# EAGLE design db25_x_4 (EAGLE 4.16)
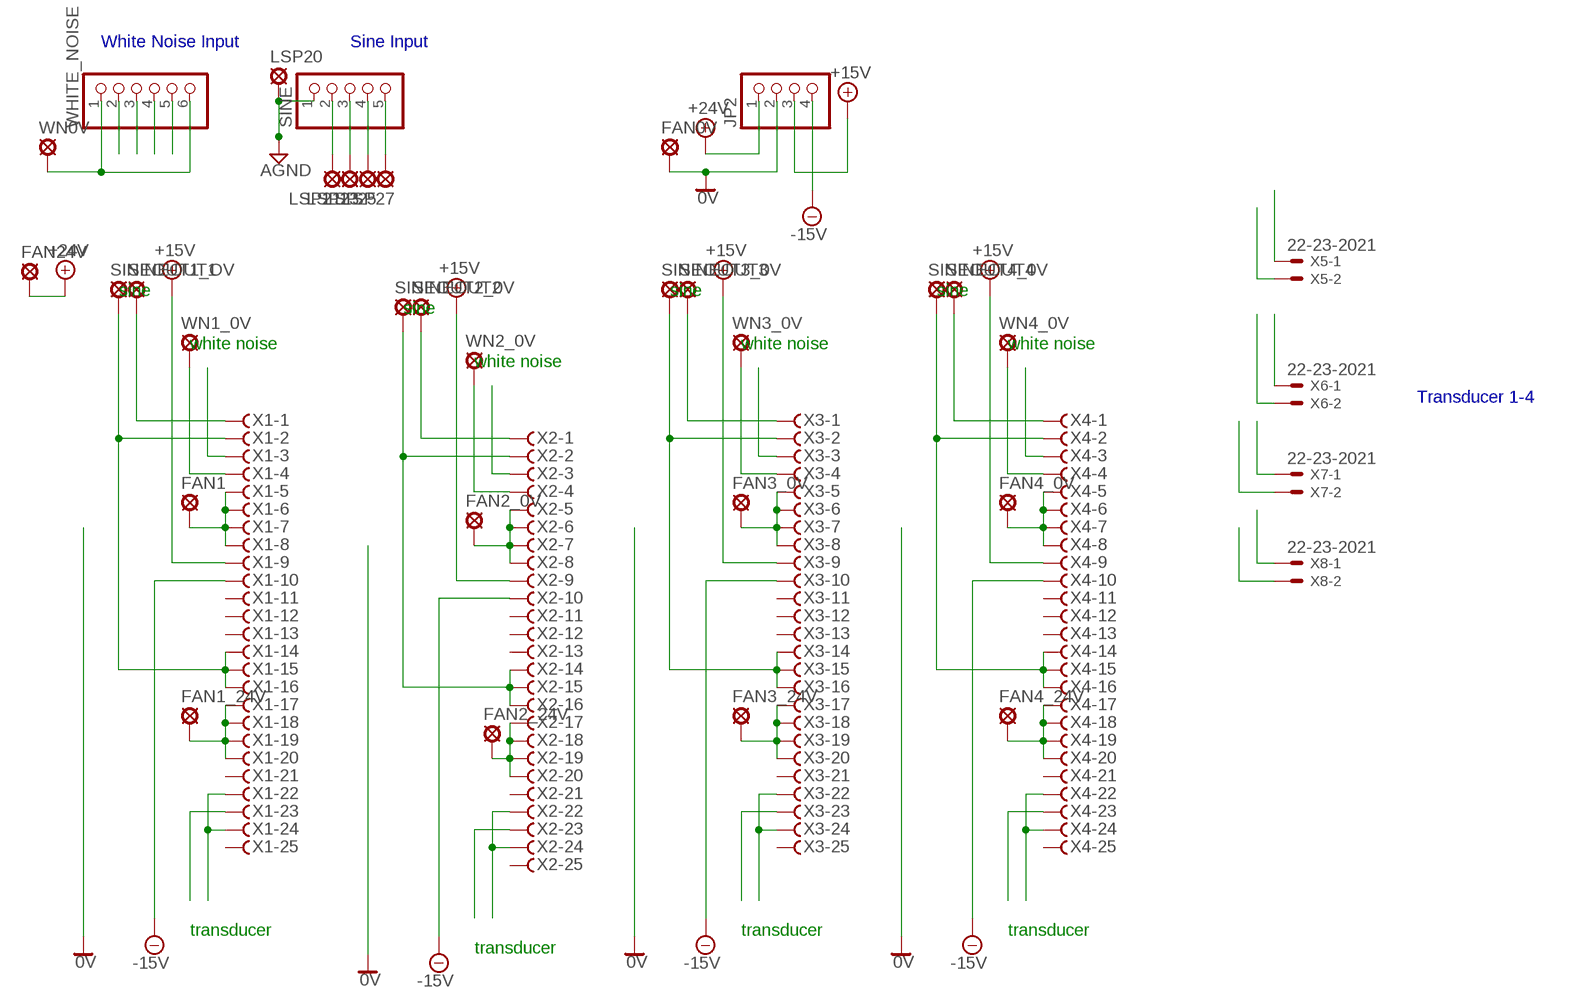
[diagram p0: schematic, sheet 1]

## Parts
FAN0V  SE14  [SE14]
FAN1  SE14  [SE14]
FAN1_24V  SE14  [SE14]
FAN2_0V  SE14  [SE14]
FAN2_24V  SE14  [SE14]
FAN3_0V  SE14  [SE14]
FAN3_24V  SE14  [SE14]
FAN4_0V  SE14  [SE14]
FAN4_24V  SE14  [SE14]
FAN24V  SE14  [SE14]
JP2  PINHD-1X4  [1X04]
LSP20  SE14  [SE14]
LSP21  SE14  [SE14]
LSP23  SE14  [SE14]
LSP25  SE14  [SE14]
LSP27  SE14  [SE14]
SINE  PINHD-1X5  [1X05]
SINEOUT1  SE14  [SE14]
SINEOUT1_OV  SE14  [SE14]
SINEOUT2  SE14  [SE14]
SINEOUT2_0V  SE14  [SE14]
SINEOUT3  SE14  [SE14]
SINEOUT3_0V  SE14  [SE14]
SINEOUT4  SE14  [SE14]
SINEOUT4_0V  SE14  [SE14]
WHITE_NOISE  PINHD-1X6  [1X06]
WN0V  SE14  [SE14]
WN1_0V  SE14  [SE14]
WN2_0V  SE14  [SE14]
WN3_0V  SE14  [SE14]
WN4_0V  SE14  [SE14]
X1  F25VS  [F25V]
X2  F25VS  [F25V]
X3  F25VS  [F25V]
X4  F25VS  [F25V]
X5  22-23-2021  [22-23-2021]
X6  22-23-2021  [22-23-2021]
X7  22-23-2021  [22-23-2021]
X8  22-23-2021  [22-23-2021]

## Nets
0V [power]: FAN0V.MP JP2.2
+15V [power]: JP2.3 X1.9 X2.9 X3.9 X4.9
+24V [power]: FAN24V.MP JP2.1
-15V [power]: JP2.4 X1.10 X2.10 X3.10 X4.10
AGND [power]: LSP20.MP SINE.1
N$1 [power]: FAN1_24V.MP X1.17 X1.18 X1.19 X1.20
N$2 [power]: FAN2_24V.MP X2.17 X2.18 X2.19 X2.20
N$3 [power]: FAN3_24V.MP X3.17 X3.18 X3.19 X3.20
N$4 [power]: FAN4_24V.MP X4.17 X4.18 X4.19 X4.20
N$5 [power]: FAN1.MP X1.5 X1.6 X1.7 X1.8
N$6 [power]: FAN2_0V.MP X2.5 X2.6 X2.7 X2.8
N$7 [power]: FAN3_0V.MP X3.5 X3.6 X3.7 X3.8
N$8 [power]: FAN4_0V.MP X4.5 X4.6 X4.7 X4.8
N$9 [power]: SINEOUT1_OV.MP X1.2 X1.14 X1.15 X1.16
N$10 [power]: SINEOUT2_0V.MP X2.2 X2.14 X2.15 X2.16
N$11 [power]: SINEOUT3_0V.MP X3.2 X3.14 X3.15 X3.16
N$12 [power]: SINEOUT4_0V.MP X4.2 X4.14 X4.15 X4.16
S1 [AF_OUT]: LSP21.MP SINE.2
S1_A [AF_OUT]: SINEOUT1.MP X1.1
S2 [AF_OUT]: LSP23.MP SINE.3
S2_A [AF_OUT]: SINEOUT2.MP X2.1
S3 [AF_OUT]: LSP25.MP SINE.4
S3_A [AF_OUT]: SINEOUT3.MP X3.1
S4 [AF_OUT]: LSP27.MP SINE.5
S4_A [AF_OUT]: SINEOUT4.MP X4.1
T1: X1.23 X5.1
T1_GND: X1.22 X1.24 X5.2
T2: X2.23 X6.1
T2_GND: X2.22 X2.24 X6.2
T3: X3.23 X7.1
T3_GND: X3.22 X3.24 X7.2
T4: X4.23 X8.1
T4_GND: X4.22 X4.24 X8.2
WN1 [AF_OUT]: WHITE_NOISE.2 X1.3
WN2 [AF_OUT]: WHITE_NOISE.3 X2.3
WN3 [AF_OUT]: WHITE_NOISE.4 X3.3
WN4 [AF_OUT]: WHITE_NOISE.5 X4.3
WN_GND [power]: WHITE_NOISE.1 WHITE_NOISE.6 WN0V.MP
WN_GND_1 [power]: WN1_0V.MP X1.4
WN_GND_2 [power]: WN2_0V.MP X2.4
WN_GND_3 [power]: WN3_0V.MP X3.4
WN_GND_4 [power]: WN4_0V.MP X4.4
Unconnected: X1.11 X1.12 X1.13 X1.21 X1.25 X2.11 X2.12 X2.13 X2.21 X2.25 X3.11 X3.12 X3.13 X3.21 X3.25 X4.11 X4.12 X4.13 X4.21 X4.25

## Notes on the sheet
- White Noise Input | Sine Input
- sine | sine | sine
- sine
- white noise | white noise | white noise
- white noise
- Transducer 1-4
- transducer | transducer | transducer
- transducer

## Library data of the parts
FAN0V FAN1 FAN1_24V FAN2_0V FAN2_24V FAN3_0V FAN3_24V FAN4_0V FAN4_24V FAN24V LSP20 LSP21 LSP23 LSP25 LSP27 SINEOUT1 SINEOUT1_OV SINEOUT2 SINEOUT2_0V SINEOUT3 SINEOUT3_0V SINEOUT4 SINEOUT4_0V WN0V WN1_0V WN2_0V WN3_0V WN4_0V = solpad:SE14: SOLDER PAD
JP2 = pinhead:PINHD-1X4: PIN HEADER
SINE = pinhead:PINHD-1X5: PIN HEADER
WHITE_NOISE = pinhead:PINHD-1X6: PIN HEADER
X1-X4 = con-subd:F25?S: SUB-D
X5-X8 = con-molex:22-23-2021: .100" (2.54mm) Center Header - 2 Pin

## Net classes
0 default: width 0.61 mm, drill 0.254 mm, clearance 0.711 mm
1 power: width 1.016 mm, drill 0.305 mm, clearance 0.813 mm
2 AF_OUT: width 1.016 mm, drill 0.305 mm, clearance 0.813 mm

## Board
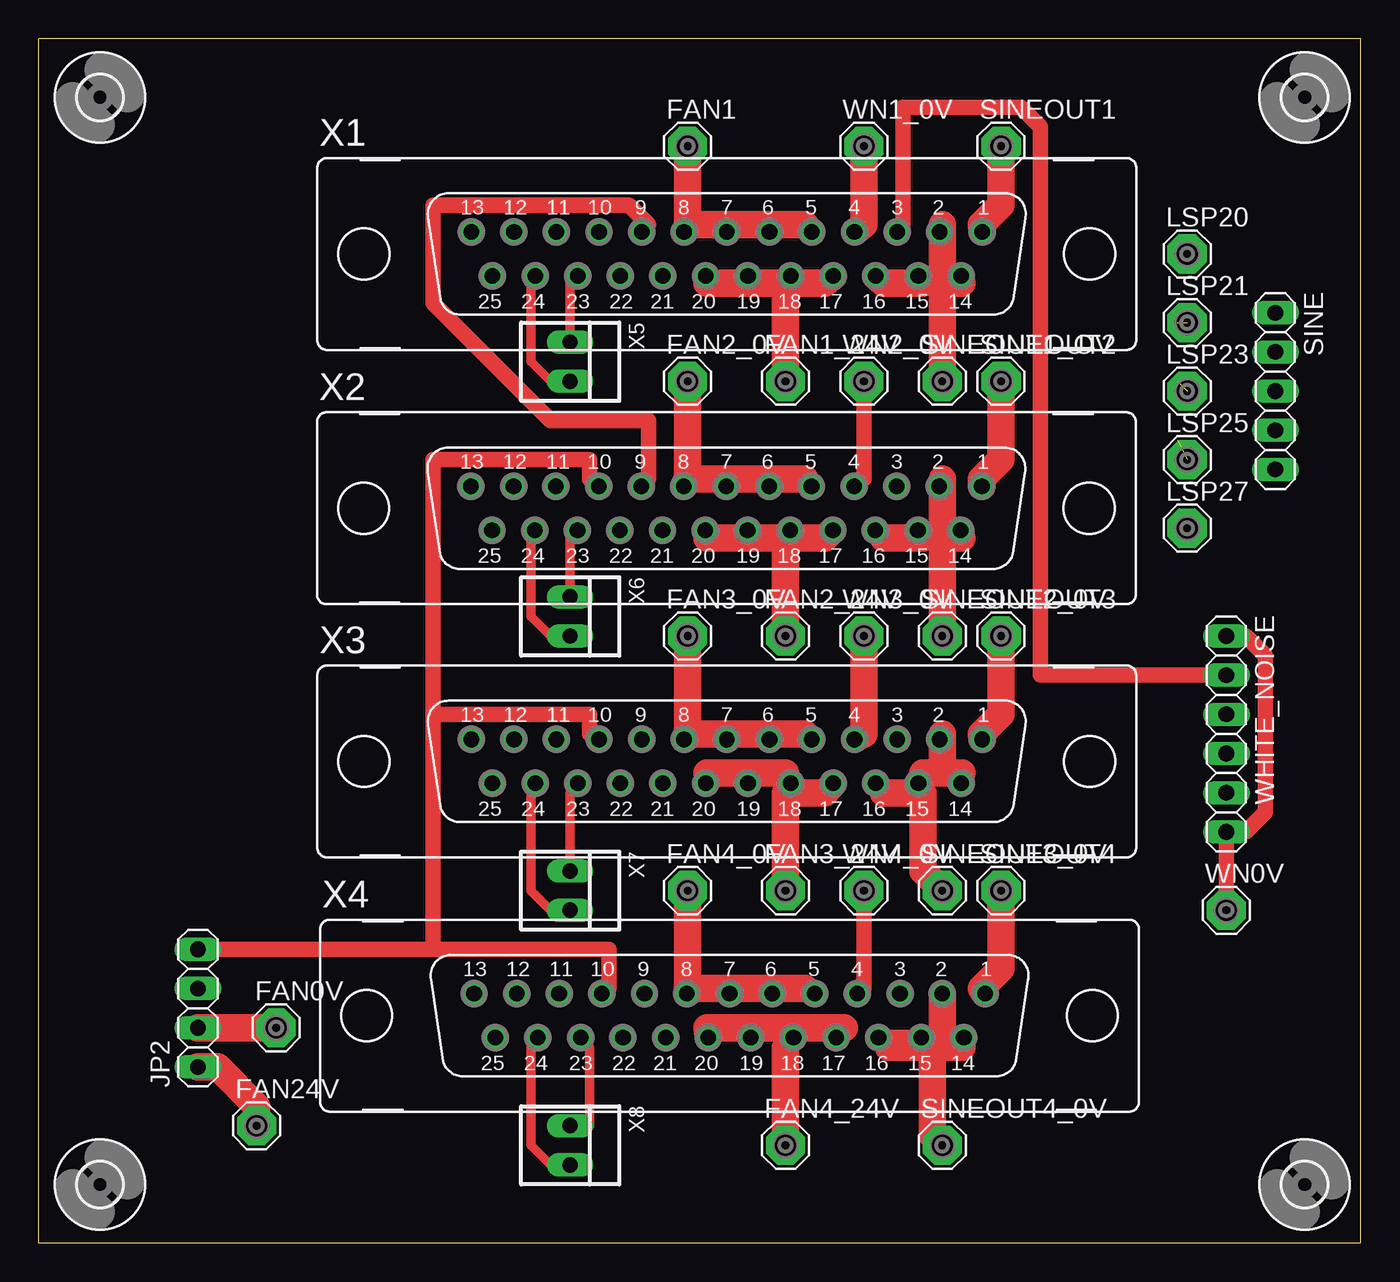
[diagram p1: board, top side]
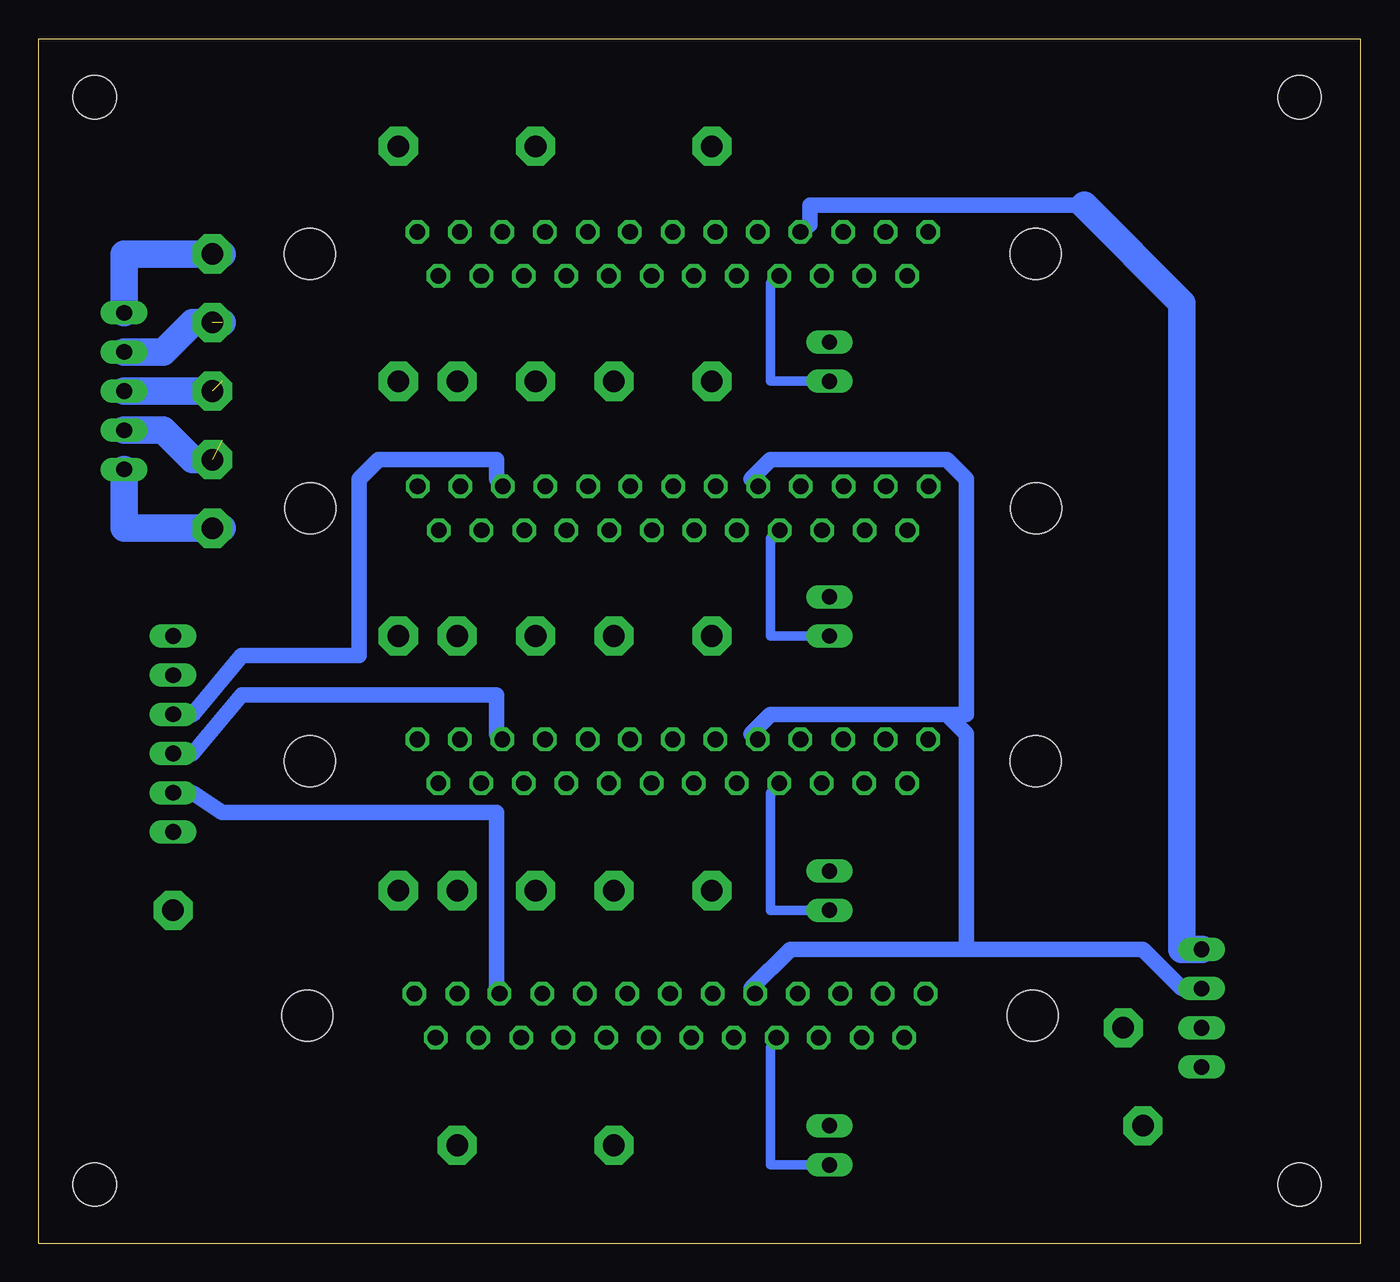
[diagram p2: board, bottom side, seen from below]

Size 85.72 x 78.1 mm. Coordinates in mm from the lower left corner, seen from the top.
Outline: 85.72,78.1 0,78.1 0,0 85.72,0 85.72,78.1
Copper layers (1*16): Top 0.035mm / dielectric 1.5mm / Bottom 0.035mm
Design rules "futurlec": minimum track width 10mil, minimum drill 28mil, track to track 10mil, track to pad 10mil, pad to pad 10mil, via to via 10mil, smd to smd 0mil, copper to edge 40mil, drill to drill 10mil, minimum pad ring 10mil, minimum via ring 8mil, stop-mask expansion 4mil, vias tented up to drill 0mil, thermal gap 10mil

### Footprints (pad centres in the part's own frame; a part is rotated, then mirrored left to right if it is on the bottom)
SE14 = drill 1.397 pad 2.54 octagon: MP 0,0
1X04 = drill 1.016 long: 1 -3.81,0; 2 -1.27,0; 3 1.27,0; 4 3.81,0
1X05 = drill 1.016 long: 1 -5.08,0; 2 -2.54,0; 3 0,0; 4 2.54,0; 5 5.08,0
2,8 = hole 2.8: 0,0
1X06 = drill 1.016 long: 1 -6.35,0; 2 -3.81,0; 3 -1.27,0; 4 1.27,0; 5 3.81,0; 6 6.35,0
F25V = drill 1.016 octagon: 1 16.561,1.422; 2 13.792,1.422; 3 11.049,1.422; 4 8.28,1.422; 5 5.512,1.422; 6 2.769,1.422; 7 0,1.422; 8 -2.769,1.422; 9 -5.512,1.422; 10 -8.28,1.422; 11 -11.049,1.422; 12 -13.792,1.422; 13 -16.561,1.422; 14 15.189,-1.422; 15 12.421,-1.422; 16 9.652,-1.422; 17 6.909,-1.422; 18 4.14,-1.422; 19 1.372,-1.422; 20 -1.372,-1.422; 21 -4.14,-1.422; 22 -6.909,-1.422; 23 -9.652,-1.422; 24 -12.421,-1.422; 25 -15.189,-1.422 | hole 3.302: 23.52,0; -23.52,0
22-23-2021 = drill 1 long: 1 -1.27,0; 2 1.27,0

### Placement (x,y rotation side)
FAN0V  15.4,13.97 0 top
FAN1  42.07,71.12 0 top
FAN1_24V  48.42,55.88 0 top
FAN2_0V  42.07,55.88 0 top
FAN2_24V  48.42,39.38 0 top
FAN3_0V  42.07,39.38 0 top
FAN3_24V  48.42,22.87 0 top
FAN4_0V  42.07,22.87 0 top
FAN4_24V  48.42,6.36 0 top
FAN24V  14.13,7.63 0 top
JP2  10.32,15.24 90 top
LSP20  74.46,64.14 0 top
LSP21  74.46,59.7 0 top
LSP23  74.46,55.25 0 top
LSP25  74.46,50.8 0 top
LSP27  74.46,46.36 0 top
SINE  80.17,55.25 270 top
SINEOUT1  62.39,71.12 0 top
SINEOUT1_OV  58.59,55.88 0 top
SINEOUT2  62.39,55.88 0 top
SINEOUT2_0V  58.59,39.38 0 top
SINEOUT3  62.39,39.38 0 top
SINEOUT3_0V  58.59,22.87 0 top
SINEOUT4  62.39,22.87 0 top
SINEOUT4_0V  58.59,6.36 0 top
U$1  [2,8]  3.97,74.3 0 top
U$2  [2,8]  3.97,3.81 0 top
U$3  [2,8]  82.08,3.81 0 top
U$4  [2,8]  82.08,74.3 0 top
WHITE_NOISE  77,33.02 270 top
WN0V  77,21.59 0 top
WN1_0V  53.5,71.12 0 top
WN2_0V  53.5,55.88 0 top
WN3_0V  53.5,39.38 0 top
WN4_0V  53.5,22.87 0 top
X1  44.61,64.14 0 top
X2  44.59,47.66 0 top
X3  44.61,31.25 0 top
X4  44.79,14.76 0 top
X5  34.45,57.16 270 top
X6  34.45,40.65 270 top
X7  34.45,22.87 270 top
X8  34.45,6.36 270 top

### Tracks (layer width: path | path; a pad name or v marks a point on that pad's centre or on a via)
0V
  Top 1.778: JP2.2 FAN0V.MP
+15V
  Top 1.016: X1.9 39.53,66.05 38.27,67.31 25.56,67.31 25.56,60.96 33.19,53.34 39.53,53.34 39.53,49.54 X2.9
  Bottom 1.016: 25.56,19.05 36.99,19.05 39.53,16.52 X4.9 | 25.56,19.05 14.13,19.05 11.59,16.52 JP2.3 | 26.84,34.3 38.27,34.3 39.53,33.02 X3.9 | 26.84,34.3 25.56,33.02 25.56,19.05 | 26.84,34.3 25.56,34.3 25.56,49.54 26.84,50.8 38.27,50.8 39.53,49.54 X2.9
+24V
  Top 1.778: FAN24V.MP 14.13,8.9 11.59,11.44 JP2.1
-15V
  Top 1.016: 25.56,19.05 36.99,19.05 36.99,16.52 X4.10 | JP2.4 25.56,19.05 | 25.56,34.3 35.73,34.3 35.73,33.02 X3.10 | 25.56,19.05 25.56,34.3 | 25.56,34.3 25.56,50.8 35.73,50.8 35.73,49.54 X2.10
  Bottom 1.016: 17.95,67.31 35.73,67.31 35.73,66.05 X1.10
  Bottom 1.778: 17.95,67.31 11.59,60.96 11.59,19.05 JP2.4
AGND
  Bottom 1.778: SINE.1 80.17,64.14 LSP20.MP 73.83,64.14
N$1
  Top 1.016: 43.34,62.24 X1.20 | 45.88,62.24 X1.19 | 48.42,62.24 X1.18
  Top 1.778: 43.34,62.24 45.88,62.24 48.42,62.24 | 48.42,62.24 50.96,62.24 X1.17 | FAN1_24V.MP 48.42,62.24
N$2
  Top 1.016: 43.34,45.73 X2.20 | 45.88,45.73 X2.19 | 48.42,45.73 X2.18
  Top 1.778: 43.34,45.73 45.88,45.73 48.42,45.73 | 48.42,45.73 50.96,45.73 X2.17 | FAN2_24V.MP 48.42,45.73
N$3
  Top 1.016: 43.34,30.48 X3.20 | 48.42,30.48 X3.18 48.42,29.22 | 45.88,30.48 X3.19
  Top 1.778: 43.34,30.48 45.88,30.48 48.42,30.48 | X3.17 50.96,29.22 48.42,29.22 FAN3_24V.MP
N$4
  Top 1.016: 45.88,13.97 X4.19 | X4.18 48.42,13.97
  Top 1.27: 52.23,13.97 X4.17 | 48.42,12.71 X4.18
  Top 1.778: X4.20 43.34,13.97 45.88,13.97 48.42,13.97 52.23,13.97 | FAN4_24V.MP 48.42,12.71
N$5
  Top 1.016: 44.61,66.05 X1.7 | 49.7,66.05 X1.5 | 47.16,66.05 X1.6
  Top 1.778: 42.07,66.05 44.61,66.05 47.16,66.05 49.7,66.05 | 42.07,66.05 FAN1.MP | X1.8 42.07,66.05
N$6
  Top 1.016: 44.61,49.54 X2.7 | 49.7,49.54 X2.5 | 47.16,49.54 X2.6
  Top 1.778: 42.07,49.54 44.61,49.54 47.16,49.54 49.7,49.54 | 42.07,49.54 FAN2_0V.MP | X2.8 42.07,49.54
N$7
  Top 1.016: 44.61,33.02 X3.7 | 49.7,33.02 X3.5 | 47.16,33.02 X3.6 | X3.8 42.07,33.02
  Top 1.778: 49.7,33.02 47.16,33.02 44.61,33.02 42.07,33.02 FAN3_0V.MP
N$8
  Top 1.016: 44.61,16.52 X4.7 | 49.7,16.52 X4.5 | 47.16,16.52 X4.6 | X4.8 42.07,16.52
  Top 1.778: 49.7,16.52 47.16,16.52 44.61,16.52 42.07,16.52 FAN4_0V.MP
N$9
  Top 1.016: 58.59,62.24 57.31,62.24 X1.15 | 59.85,62.24 X1.14 | 58.59,66.05 X1.2
  Top 1.778: 57.31,62.24 54.77,62.24 X1.16 | 58.59,62.24 59.85,62.24 | 58.59,62.24 58.59,66.05 | SINEOUT1_OV.MP 58.59,62.24
N$10
  Top 1.016: 54.77,45.73 X2.16 | 58.59,45.73 57.31,45.73 X2.15 | 59.85,45.73 X2.14 | 58.59,49.54 X2.2
  Top 1.778: 57.31,45.73 54.77,45.73 | 58.59,45.73 59.85,45.73 | 58.59,45.73 58.59,49.54 | SINEOUT2_0V.MP 58.59,45.73
N$11
  Top 1.016: 54.77,29.22 X3.16 | 59.85,30.48 X3.14 | 57.31,30.48 X3.15 57.31,29.22 | 58.59,33.02 X3.2
  Top 1.778: 54.77,29.22 57.31,29.22 57.31,24.14 SINEOUT3_0V.MP | 57.31,30.48 58.59,30.48 | 58.59,30.48 59.85,30.48 | 58.59,30.48 58.59,33.02
N$12
  Top 1.016: 55.08,12.71 X4.16 | 58.59,13.97 59.85,12.71 59.85,13.34 X4.14 | X4.2 58.59,16.52 | X4.16 54.14,13.34 | X4.16 X4.15 | SINEOUT4_0V.MP 57.95,6.99
  Top 1.778: 57.95,12.71 55.08,12.71 | 57.95,12.71 59.85,12.71 | 58.59,13.97 X4.2 | 57.95,6.99 57.95,12.71
S1  (1 unrouted)
  Bottom 1.778: SINE.2 77.63,57.79 75.73,59.7 73.83,59.7
S1_A
  Top 1.778: SINEOUT1.MP 62.39,67.31 61.12,66.05 X1.1
S2  (1 unrouted)
  Bottom 1.778: SINE.3 LSP23.MP
S2_A
  Top 1.778: SINEOUT2.MP 62.39,50.8 61.12,49.54 X2.1
S3  (1 unrouted)
  Bottom 1.778: SINE.4 77.63,52.71 75.73,50.8 LSP25.MP
S3_A
  Top 1.778: SINEOUT3.MP 62.39,34.3 61.12,33.02 X3.1
S4
  Bottom 1.778: SINE.5 80.17,46.36 LSP27.MP 73.83,46.36
S4_A
  Top 1.778: SINEOUT4.MP 62.39,17.79 61.12,16.52 X4.1
T1
  Top 0.61: X5.1 34.45,62.24 X1.23
T1_GND
  Top 0.61: X5.2 33.19,55.88 31.91,57.16 31.91,62.24 X1.24
  Bottom 0.61: X1.22 38.27,62.24 38.27,55.88 X5.2
T2
  Top 0.61: X6.1 34.45,45.73 X2.23
T2_GND
  Top 0.61: X6.2 33.19,39.38 31.91,40.65 31.91,45.73 X2.24
  Bottom 0.61: X2.22 38.27,45.73 38.27,39.38 X6.2
T3
  Top 0.61: X7.1 34.45,29.22 X3.23
T3_GND
  Top 0.61: X7.2 33.19,21.59 31.91,22.87 31.91,29.22 X3.24
  Bottom 0.61: X3.22 38.27,29.22 38.27,21.59 X7.2
T4
  Top 0.61: X8.1 35.73,7.63 35.73,12.71 X4.23
T4_GND
  Top 0.61: X8.2 33.19,5.09 31.91,6.36 31.91,12.71 X4.24
  Bottom 0.61: X4.22 38.27,12.71 38.27,5.09 X8.2
WN1
  Top 1.016: WHITE_NOISE.2 64.94,36.84 64.94,72.39 63.66,73.66 56.04,73.66 56.04,66.05 X1.3
WN2
  Bottom 1.016: X2.3 56.04,49.54 56.04,50.8 63.66,50.8 64.94,49.54 64.94,38.11 72.56,38.11 75.73,34.3 WHITE_NOISE.3
WN3
  Bottom 1.016: X3.3 56.04,33.02 56.04,35.57 72.56,35.57 75.73,31.76 WHITE_NOISE.4
WN4
  Bottom 1.016: X4.3 56.04,16.52 56.04,27.95 73.83,27.95 75.73,29.22 WHITE_NOISE.5
WN_GND
  Top 1.016: WN0V.MP WHITE_NOISE.6 78.27,26.68 79.54,27.95 79.54,38.11 78.27,39.38 WHITE_NOISE.1
WN_GND_1
  Top 1.778: WN1_0V.MP 53.5,66.05 X1.4
WN_GND_2
  Top 1.016: WN2_0V.MP 53.5,49.54 X2.4
WN_GND_3
  Top 1.778: WN3_0V.MP 53.5,33.02 X3.4
WN_GND_4
  Top 1.016: WN4_0V.MP 53.5,16.52 X4.4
